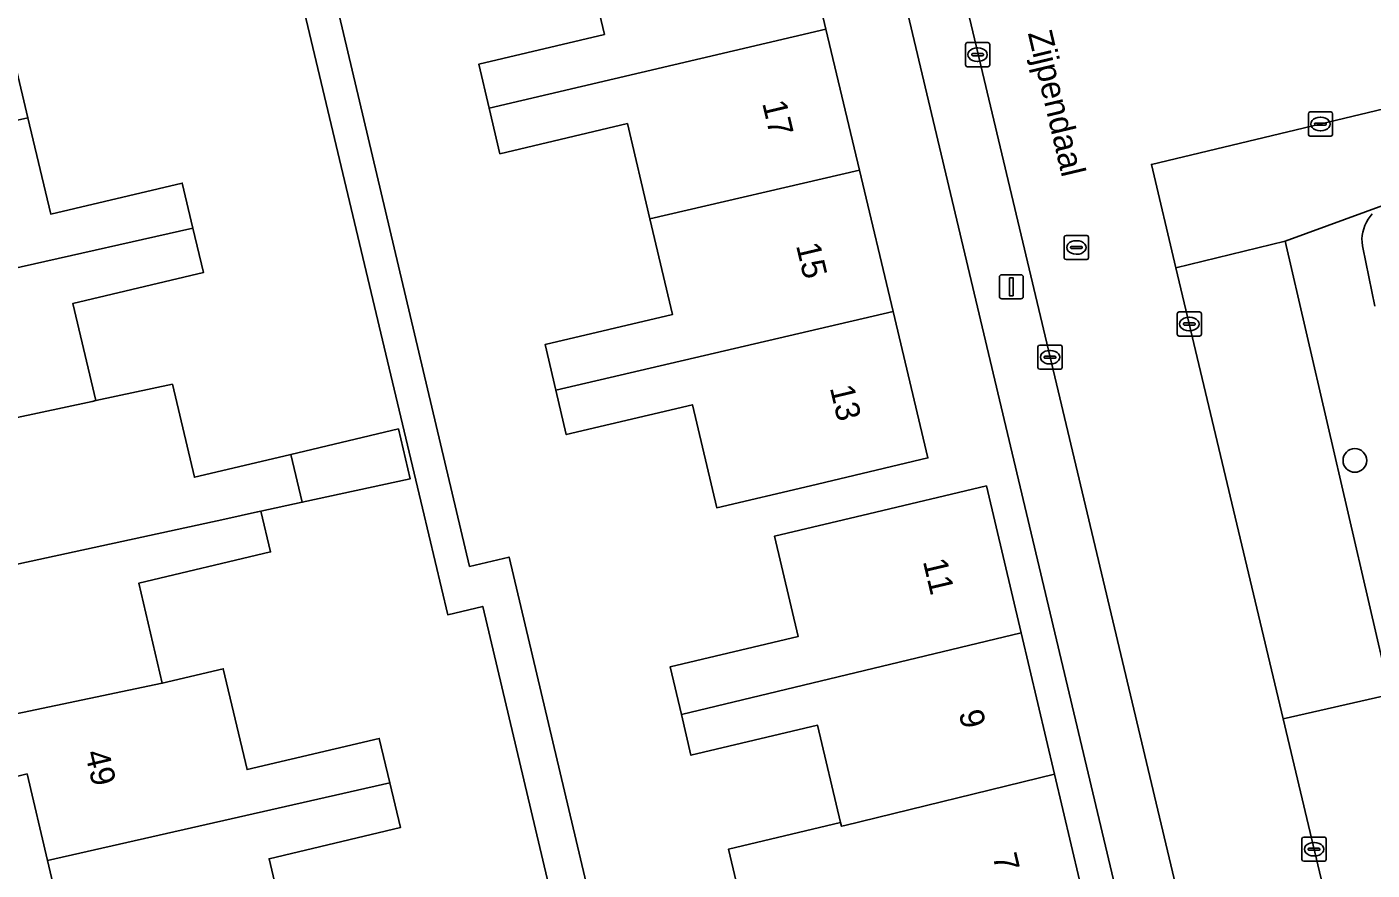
# Model space of a CAD drawing. Extents: x 158031 to 159244, y 380104 to 381214.
# Drawn here: x 158412.4 to 158468.1, y 380704.1 to 380739 of the extents above; entities that cross this region are included whole.
import ezdxf

# ---------------------------------------------------------------- set-up
doc = ezdxf.new("R2010")
doc.units = 0
for name, color, linetype in [('IMGEO_Boom', 7, 'Continuous'), ('IMGEO_Erf', 7, 'Continuous'), ('IMGEO_Kolk', 7, 'Continuous'), ('IMGEO_Lichtmast', 7, 'Continuous'), ('IMGEO_Openbare_ruimte_label', 7, 'Continuous'), ('IMGEO_Pand', 7, 'Continuous'), ('IMGEO_Pand_nummerreeks', 7, 'Continuous'), ('IMGEO_Parkeervlak_open', 7, 'Continuous'), ('IMGEO_Rijbaan_lokaal_open', 7, 'Continuous'), ('IMGEO_Rioolput', 7, 'Continuous'), ('IMGEO_Voetpad_open', 7, 'Continuous')]:
    doc.layers.add(name, color=color, linetype=linetype)

msp = doc.modelspace()

# ---------------------------------------------------------------- linework, layer by layer
at = {"layer": 'IMGEO_Boom'}
msp.add_circle((158467.378, 380721.065), 0.489, dxfattribs=at)
at = {"layer": 'IMGEO_Erf'}
for points in [[(158414.008, 380787.381), (158430.734, 380716.678), (158432.369, 380717.065), (158439.722, 380685.987)], [(158417.108, 380670.868), (158417.251, 380670.908), (158427.098, 380673.251), (158437.459, 380675.717), (158436.713, 380678.868), (158435.288, 380684.889), (158438.251, 380685.59), (158431.284, 380715.029), (158429.83, 380714.683), (158428.781, 380719.094), (158421.435, 380749.975)], [(158462.621, 380681.705), (158446.395, 380750)], [(158444.097, 380744.746), (158445.485, 380738.91), (158446.873, 380733.075), (158448.264, 380727.229), (158449.705, 380721.172), (158444.84, 380720.021), (158440.965, 380719.105), (158439.956, 380723.37), (158434.738, 380722.135), (158434.305, 380723.968), (158433.858, 380725.856), (158439.136, 380727.104), (158438.201, 380731.055), (158437.268, 380735.001), (158431.989, 380733.753), (158431.543, 380735.635), (158431.112, 380737.457), (158436.318, 380738.689), (158435.358, 380742.748)], [(158411.491, 380739.326), (158412.458, 380735.237), (158413.401, 380731.253), (158418.841, 380732.54), (158419.282, 380730.676), (158419.716, 380728.838), (158414.318, 380727.561), (158415.269, 380723.541), (158418.438, 380724.215), (158419.347, 380720.372), (158421.642, 380720.915), (158423.338, 380721.316), (158427.791, 380722.369), (158428.279, 380720.308), (158423.807, 380719.336), (158422.102, 380718.972), (158422.502, 380717.28), (158417.039, 380715.987), (158418.018, 380711.85), (158420.54, 380712.447), (158421.528, 380708.274), (158427, 380709.568), (158427.435, 380707.728), (158427.874, 380705.875), (158422.44, 380704.589), (158423.384, 380700.598)], [(158468.101, 380731.266), (158468.008, 380731.157), (158467.925, 380731.04), (158467.854, 380730.916), (158467.793, 380730.787), (158467.744, 380730.652), (158467.708, 380730.514), (158467.684, 380730.373), (158467.673, 380730.231), (158467.674, 380730.088), (158467.689, 380729.945), (158467.702, 380729.868), (158468.21, 380727.452)], [(158442.408, 380700.976), (158441.458, 380704.991), (158446.09, 380706.086), (158445.138, 380710.109), (158439.9, 380708.869), (158439.502, 380710.55), (158439.036, 380712.522), (158444.335, 380713.775), (158443.351, 380717.931), (158447.263, 380718.857), (158452.128, 380720.008), (158453.566, 380713.928), (158454.95, 380708.081), (158456.33, 380702.244)], [(158414.113, 380700.942), (158413.268, 380704.515), (158412.421, 380708.094), (158411.07, 380707.775)]]:
    msp.add_lwpolyline(points, dxfattribs=at)
at = {"layer": 'IMGEO_Kolk'}
for p, q in [((158451.262, 380737.425), (158451.262, 380738.277)), ((158451.337, 380738.351), (158452.189, 380738.351)), ((158451.75, 380738.131), (158451.775, 380738.131)), ((158452.263, 380738.277), (158452.263, 380737.425)), ((158451.521, 380737.845), (158451.521, 380737.857)), ((158451.959, 380737.808), (158451.561, 380737.808)), ((158451.564, 380737.894), (158451.962, 380737.894)), ((158451.773, 380737.571), (158451.748, 380737.571)), ((158452.005, 380737.857), (158452.005, 380737.845)), ((158452.189, 380737.351), (158451.337, 380737.351)), ((158465.454, 380734.553), (158465.454, 380735.405)), ((158465.529, 380735.479), (158466.381, 380735.479)), ((158465.942, 380735.259), (158465.967, 380735.259)), ((158466.455, 380735.405), (158466.455, 380734.553)), ((158465.713, 380734.973), (158465.713, 380734.985)), ((158466.151, 380734.936), (158465.753, 380734.936)), ((158465.756, 380735.022), (158466.154, 380735.022)), ((158465.965, 380734.699), (158465.94, 380734.699)), ((158466.197, 380734.985), (158466.197, 380734.973)), ((158466.381, 380734.479), (158465.529, 380734.479)), ((158460.025, 380726.282), (158460.025, 380727.134)), ((158460.1, 380727.208), (158460.952, 380727.208)), ((158460.513, 380726.988), (158460.538, 380726.988)), ((158461.026, 380727.134), (158461.026, 380726.282)), ((158460.284, 380726.702), (158460.284, 380726.714)), ((158460.722, 380726.665), (158460.324, 380726.665)), ((158460.327, 380726.751), (158460.725, 380726.751)), ((158460.536, 380726.428), (158460.511, 380726.428)), ((158460.768, 380726.714), (158460.768, 380726.702)), ((158454.262, 380724.909), (158454.262, 380725.761)), ((158454.337, 380725.835), (158455.189, 380725.835)), ((158455.263, 380725.761), (158455.263, 380724.909)), ((158460.952, 380726.208), (158460.1, 380726.208)), ((158454.521, 380725.329), (158454.521, 380725.341)), ((158454.959, 380725.292), (158454.561, 380725.292)), ((158454.564, 380725.378), (158454.962, 380725.378)), ((158454.75, 380725.615), (158454.775, 380725.615)), ((158455.005, 380725.341), (158455.005, 380725.329)), ((158455.189, 380724.835), (158454.337, 380724.835)), ((158454.773, 380725.055), (158454.748, 380725.055)), ((158465.189, 380704.556), (158465.189, 380705.408)), ((158465.264, 380705.482), (158466.116, 380705.482)), ((158465.677, 380705.262), (158465.702, 380705.262)), ((158466.19, 380705.408), (158466.19, 380704.556)), ((158465.448, 380704.976), (158465.448, 380704.988)), ((158465.886, 380704.939), (158465.488, 380704.939)), ((158465.491, 380705.025), (158465.889, 380705.025)), ((158465.7, 380704.702), (158465.675, 380704.702)), ((158465.932, 380704.988), (158465.932, 380704.976)), ((158466.116, 380704.482), (158465.264, 380704.482))]:
    msp.add_line(p, q, dxfattribs=at)
for points in [[(158451.262, 380737.425), (158451.262, 380738.277)], [(158451.337, 380738.351), (158452.189, 380738.351)], [(158452.263, 380738.277), (158452.263, 380737.425)], [(158452.189, 380737.351), (158451.337, 380737.351)], [(158465.454, 380734.553), (158465.454, 380735.405)], [(158465.529, 380735.479), (158466.381, 380735.479)], [(158466.455, 380735.405), (158466.455, 380734.553)], [(158466.381, 380734.479), (158465.529, 380734.479)], [(158460.025, 380726.282), (158460.025, 380727.134)], [(158460.1, 380727.208), (158460.952, 380727.208)], [(158461.026, 380727.134), (158461.026, 380726.282)], [(158454.262, 380724.909), (158454.262, 380725.761)], [(158454.337, 380725.835), (158455.189, 380725.835)], [(158455.263, 380725.761), (158455.263, 380724.909)], [(158460.952, 380726.208), (158460.1, 380726.208)], [(158455.189, 380724.835), (158454.337, 380724.835)], [(158465.189, 380704.556), (158465.189, 380705.408)], [(158465.264, 380705.482), (158466.116, 380705.482)], [(158466.19, 380705.408), (158466.19, 380704.556)], [(158466.116, 380704.482), (158465.264, 380704.482)]]:
    msp.add_lwpolyline(points, dxfattribs=at)
for centre, radius, start, end in [((158451.339, 380738.275), 0.0765, 91.552, 178.448), ((158451.339, 380738.275), 0.0765, 91.552, 178.448), ((158452.187, 380738.275), 0.0765, 1.552, 88.448), ((158452.187, 380738.275), 0.0765, 1.552, 88.448), ((158451.339, 380737.427), 0.0765, 181.552, 268.448), ((158451.339, 380737.427), 0.0765, 181.552, 268.448), ((158451.561, 380737.854), 0.0403, 85.8775, 175.7526), ((158451.558, 380737.844), 0.0366, 178.938, 274.7102), ((158451.962, 380737.851), 0.043, 264.8664, 352.4533), ((158451.966, 380737.856), 0.0386, 1.7309, 96.639), ((158452.187, 380737.427), 0.0765, 271.552, 358.448), ((158452.187, 380737.427), 0.0765, 271.552, 358.448), ((158465.531, 380735.403), 0.0765, 91.552, 178.448), ((158465.531, 380735.403), 0.0765, 91.552, 178.448), ((158466.379, 380735.403), 0.0765, 1.552, 88.448), ((158466.379, 380735.403), 0.0765, 1.552, 88.448), ((158465.753, 380734.982), 0.0403, 85.8775, 175.7526), ((158465.75, 380734.972), 0.0366, 178.938, 274.7102), ((158466.154, 380734.979), 0.043, 264.8664, 352.4533), ((158466.158, 380734.984), 0.0386, 1.7309, 96.639), ((158465.531, 380734.555), 0.0765, 181.552, 268.448), ((158465.531, 380734.555), 0.0765, 181.552, 268.448), ((158466.379, 380734.555), 0.0765, 271.552, 358.448), ((158466.379, 380734.555), 0.0765, 271.552, 358.448), ((158460.102, 380727.132), 0.0765, 91.552, 178.448), ((158460.102, 380727.132), 0.0765, 91.552, 178.448), ((158460.95, 380727.132), 0.0765, 1.552, 88.448), ((158460.95, 380727.132), 0.0765, 1.552, 88.448), ((158460.102, 380726.284), 0.0765, 181.552, 268.448), ((158460.102, 380726.284), 0.0765, 181.552, 268.448), ((158460.324, 380726.711), 0.0403, 85.8775, 175.7526), ((158460.321, 380726.701), 0.0366, 178.938, 274.7102), ((158460.725, 380726.708), 0.043, 264.8664, 352.4533), ((158460.729, 380726.713), 0.0386, 1.7309, 96.639), ((158460.95, 380726.284), 0.0765, 271.552, 358.448), ((158460.95, 380726.284), 0.0765, 271.552, 358.448), ((158454.339, 380725.759), 0.0765, 91.552, 178.448), ((158454.339, 380725.759), 0.0765, 91.552, 178.448), ((158455.187, 380725.759), 0.0765, 1.552, 88.448), ((158455.187, 380725.759), 0.0765, 1.552, 88.448), ((158454.561, 380725.338), 0.0403, 85.8775, 175.7526), ((158454.558, 380725.328), 0.0366, 178.938, 274.7102), ((158454.962, 380725.335), 0.043, 264.8664, 352.4533), ((158454.966, 380725.34), 0.0386, 1.7309, 96.639), ((158454.339, 380724.911), 0.0765, 181.552, 268.448), ((158454.339, 380724.911), 0.0765, 181.552, 268.448), ((158455.187, 380724.911), 0.0765, 271.552, 358.448), ((158455.187, 380724.911), 0.0765, 271.552, 358.448), ((158465.266, 380705.406), 0.0765, 91.552, 178.448), ((158465.266, 380705.406), 0.0765, 91.552, 178.448), ((158466.114, 380705.406), 0.0765, 1.552, 88.448), ((158466.114, 380705.406), 0.0765, 1.552, 88.448), ((158465.266, 380704.558), 0.0765, 181.552, 268.448), ((158465.266, 380704.558), 0.0765, 181.552, 268.448), ((158465.488, 380704.985), 0.0403, 85.8775, 175.7526), ((158465.485, 380704.975), 0.0366, 178.938, 274.7102), ((158465.889, 380704.982), 0.043, 264.8664, 352.4533), ((158465.893, 380704.987), 0.0386, 1.7309, 96.639), ((158466.114, 380704.558), 0.0765, 271.552, 358.448), ((158466.114, 380704.558), 0.0765, 271.552, 358.448)]:
    msp.add_arc(centre, radius, start, end, dxfattribs=at)
for centre, major_axis, ratio, start_param, end_param in [((158451.749, 380737.851), (-0.387, 0.002), 0.722429, 4.712389, 7.853982), ((158451.774, 380737.851), (-0.39, 0.002), 0.717154, 1.570796, 4.712389), ((158465.941, 380734.979), (-0.387, 0.002), 0.722429, 4.712389, 7.853982), ((158465.966, 380734.979), (-0.39, 0.002), 0.717154, 1.570796, 4.712389), ((158460.512, 380726.708), (-0.387, 0.002), 0.722429, 4.712389, 7.853982), ((158460.537, 380726.708), (-0.39, 0.002), 0.717154, 1.570796, 4.712389), ((158454.749, 380725.335), (-0.387, 0.002), 0.722429, 4.712389, 7.853982), ((158454.774, 380725.335), (-0.39, 0.002), 0.717154, 1.570796, 4.712389), ((158465.676, 380704.982), (-0.387, 0.002), 0.722429, 4.712389, 7.853982), ((158465.701, 380704.982), (-0.39, 0.002), 0.717154, 1.570796, 4.712389)]:
    msp.add_ellipse(centre, major_axis=major_axis, ratio=ratio, start_param=start_param, end_param=end_param, dxfattribs=at)
at = {"layer": 'IMGEO_Lichtmast'}
for p, q in [((158452.663, 380727.849), (158452.663, 380728.649)), ((158452.663, 380728.649), (158452.663, 380727.849)), ((158452.763, 380728.749), (158453.553, 380728.749)), ((158453.553, 380728.749), (158452.763, 380728.749)), ((158453.653, 380728.649), (158453.653, 380727.849)), ((158453.653, 380727.849), (158453.653, 380728.649)), ((158453.553, 380727.749), (158452.763, 380727.749)), ((158452.763, 380727.749), (158453.553, 380727.749))]:
    msp.add_line(p, q, dxfattribs=at)
msp.add_lwpolyline([(158453.083, 380728.624), (158453.233, 380728.624), (158453.233, 380727.874), (158453.083, 380727.874), (158453.083, 380728.624)], dxfattribs=at)
for centre, start, end in [((158452.763, 380728.649), 90, 180), ((158452.763, 380728.649), 90, 180), ((158453.553, 380728.649), 0, 90), ((158453.553, 380728.649), 360, 90), ((158452.763, 380727.849), 180, 270), ((158452.763, 380727.849), 180, 270), ((158453.553, 380727.849), 270, 0), ((158453.553, 380727.849), 270, 0)]:
    msp.add_arc(centre, 0.1, start, end, dxfattribs=at)
at = {"layer": 'IMGEO_Pand'}
for points in [[(158445.485, 380738.91), (158444.097, 380744.746), (158435.358, 380742.748), (158436.318, 380738.689), (158431.112, 380737.457), (158431.543, 380735.635)], [(158416.475, 380742.36), (158402.31, 380739.086), (158403.685, 380733.276), (158412.458, 380735.237), (158411.491, 380739.326), (158416.891, 380740.603)], [(158445.485, 380738.91), (158431.543, 380735.635), (158431.989, 380733.753), (158437.268, 380735.001), (158438.201, 380731.055), (158446.873, 380733.075)], [(158419.282, 380730.676), (158418.841, 380732.54), (158413.401, 380731.253), (158412.458, 380735.237), (158403.685, 380733.276), (158405.057, 380727.476)], [(158448.264, 380727.229), (158446.873, 380733.075), (158438.201, 380731.055), (158439.136, 380727.104), (158433.858, 380725.856), (158434.305, 380723.968)], [(158419.282, 380730.676), (158405.057, 380727.476), (158406.434, 380721.657), (158415.116, 380723.503), (158415.269, 380723.541), (158414.318, 380727.561), (158419.716, 380728.838)], [(158448.264, 380727.229), (158434.305, 380723.968), (158434.738, 380722.135), (158439.956, 380723.37), (158440.965, 380719.105), (158444.84, 380720.021), (158449.705, 380721.172)], [(158415.269, 380723.541), (158415.116, 380723.503), (158406.434, 380721.657), (158407.806, 380715.857), (158420.607, 380718.64), (158421.958, 380718.934), (158422.102, 380718.972), (158423.807, 380719.336), (158423.338, 380721.316), (158421.642, 380720.915), (158419.347, 380720.372), (158418.438, 380724.215)], [(158423.338, 380721.316), (158423.807, 380719.336), (158428.279, 380720.308), (158427.791, 380722.369)], [(158453.566, 380713.928), (158452.128, 380720.008), (158447.263, 380718.857), (158443.351, 380717.931), (158444.335, 380713.775), (158439.036, 380712.522), (158439.502, 380710.55)], [(158417.039, 380715.987), (158422.502, 380717.28), (158422.102, 380718.972), (158421.958, 380718.934), (158420.607, 380718.64), (158407.806, 380715.857), (158409.191, 380710), (158418.018, 380711.85)], [(158453.566, 380713.928), (158439.502, 380710.55), (158439.9, 380708.869), (158445.138, 380710.109), (158446.09, 380706.086), (158446.126, 380705.935), (158446.274, 380705.968), (158454.95, 380708.081)], [(158418.018, 380711.85), (158409.191, 380710), (158409.228, 380709.845), (158410.509, 380710.148), (158411.07, 380707.775), (158412.421, 380708.094), (158413.268, 380704.515), (158427.435, 380707.728), (158427, 380709.568), (158421.528, 380708.274), (158420.54, 380712.447)], [(158454.95, 380708.081), (158446.274, 380705.968), (158446.126, 380705.935), (158446.09, 380706.086), (158441.458, 380704.991), (158442.408, 380700.976), (158441.727, 380700.815), (158442.208, 380698.782), (158456.33, 380702.244)], [(158413.303, 380698.346), (158423.384, 380700.598), (158422.44, 380704.589), (158427.874, 380705.875), (158427.435, 380707.728), (158413.268, 380704.515), (158414.113, 380700.942), (158412.764, 380700.622)]]:
    msp.add_lwpolyline(points, close=True, dxfattribs=at)
at = {"layer": 'IMGEO_Parkeervlak_open'}
msp.add_lwpolyline([(158464.407, 380710.377), (158468.845, 380711.378), (158464.494, 380730.142), (158459.972, 380729.032)], close=True, dxfattribs=at)
at = {"layer": 'IMGEO_Rijbaan_lokaal_open'}
msp.add_lwpolyline([(158465.25, 380776.353), (158458.389, 380774.771), (158448.498, 380772.49), (158443.849, 380771.419), (158448.9, 380750), (158465.02, 380682.236), (158470.774, 380683.592), (158470.103, 380686.415), (158466.174, 380702.945), (158464.407, 380710.377), (158459.972, 380729.032), (158458.956, 380733.307), (158474.565, 380737.039), (158471.494, 380750)], close=True, dxfattribs=at)
at = {"layer": 'IMGEO_Rioolput'}
for p, q in [((158455.352, 380729.448), (158455.352, 380730.3)), ((158455.427, 380730.374), (158456.279, 380730.374)), ((158456.353, 380730.3), (158456.353, 380729.448)), ((158455.611, 380729.868), (158455.611, 380729.88)), ((158456.049, 380729.831), (158455.651, 380729.831)), ((158455.654, 380729.917), (158456.052, 380729.917)), ((158455.84, 380730.154), (158455.865, 380730.154)), ((158456.095, 380729.88), (158456.095, 380729.868)), ((158456.279, 380729.374), (158455.427, 380729.374)), ((158455.863, 380729.594), (158455.838, 380729.594))]:
    msp.add_line(p, q, dxfattribs=at)
for points in [[(158455.352, 380729.448), (158455.352, 380730.3)], [(158455.427, 380730.374), (158456.279, 380730.374)], [(158456.353, 380730.3), (158456.353, 380729.448)], [(158456.279, 380729.374), (158455.427, 380729.374)]]:
    msp.add_lwpolyline(points, dxfattribs=at)
for centre, radius, start, end in [((158455.429, 380730.298), 0.0765, 91.552, 178.448), ((158455.429, 380730.298), 0.0765, 91.552, 178.448), ((158456.277, 380730.298), 0.0765, 1.552, 88.448), ((158456.277, 380730.298), 0.0765, 1.552, 88.448), ((158455.651, 380729.877), 0.0403, 85.8775, 175.7526), ((158455.648, 380729.867), 0.0366, 178.938, 274.7102), ((158456.052, 380729.874), 0.043, 264.8664, 352.4533), ((158456.056, 380729.879), 0.0386, 1.7309, 96.639), ((158455.429, 380729.45), 0.0765, 181.552, 268.448), ((158455.429, 380729.45), 0.0765, 181.552, 268.448), ((158456.277, 380729.45), 0.0765, 271.552, 358.448), ((158456.277, 380729.45), 0.0765, 271.552, 358.448)]:
    msp.add_arc(centre, radius, start, end, dxfattribs=at)
for centre, major_axis, ratio, start_param, end_param in [((158455.839, 380729.874), (-0.387, 0.002), 0.722429, 4.712389, 7.853982), ((158455.864, 380729.874), (-0.39, 0.002), 0.717154, 1.570796, 4.712389)]:
    msp.add_ellipse(centre, major_axis=major_axis, ratio=ratio, start_param=start_param, end_param=end_param, dxfattribs=at)
at = {"layer": 'IMGEO_Voetpad_open'}
msp.add_lwpolyline([(158448.9, 380750), (158443.849, 380771.419), (158440.318, 380786.43), (158438.744, 380793.123), (158436.282, 380792.566), (158446.395, 380750), (158462.621, 380681.705), (158465.02, 380682.236)], close=True, dxfattribs=at)
for points in [[(158421.435, 380749.975), (158428.781, 380719.094), (158429.83, 380714.683), (158431.284, 380715.029), (158438.251, 380685.59), (158439.676, 380679.569), (158436.713, 380678.868), (158437.459, 380675.717), (158441.902, 380676.775), (158441.16, 380679.909), (158439.722, 380685.987), (158432.369, 380717.065), (158430.734, 380716.678), (158414.008, 380787.381)], [(158474.565, 380737.039), (158458.956, 380733.307), (158459.972, 380729.032), (158464.494, 380730.142), (158468.687, 380731.665)], [(158468.687, 380731.665), (158464.494, 380730.142), (158468.845, 380711.378), (158464.407, 380710.377), (158466.174, 380702.945), (158470.632, 380703.986)], [(158468.21, 380727.452), (158467.702, 380729.868), (158467.689, 380729.945), (158467.674, 380730.088), (158467.673, 380730.231), (158467.684, 380730.373), (158467.708, 380730.514), (158467.744, 380730.652), (158467.793, 380730.787), (158467.854, 380730.916), (158467.925, 380731.04), (158468.008, 380731.157), (158468.101, 380731.266)]]:
    msp.add_lwpolyline(points, dxfattribs=at)

# ---------------------------------------------------------------- texts
at = {"layer": 'IMGEO_Openbare_ruimte_label'}
msp.add_text('Zijpendaal', height=1, rotation=283.3553, dxfattribs=at).set_placement((158453.839, 380738.74))
at = {"layer": 'IMGEO_Pand_nummerreeks'}
for s, rotation, p in [('17', 283.3824, (158442.842, 380735.846)), ('15', 283.3824, (158444.243, 380729.959)), ('13', 283.3824, (158445.643, 380724.072)), ('11', 283.3095, (158449.494, 380716.895)), ('9', 283.3096, (158450.976, 380710.631)), ('49', 283.3679, (158414.806, 380708.974)), ('7', 283.3096, (158452.378, 380704.704))]:
    msp.add_text(s, height=1, rotation=rotation, dxfattribs=at).set_placement(p)

doc.saveas('drawing.dxf')
